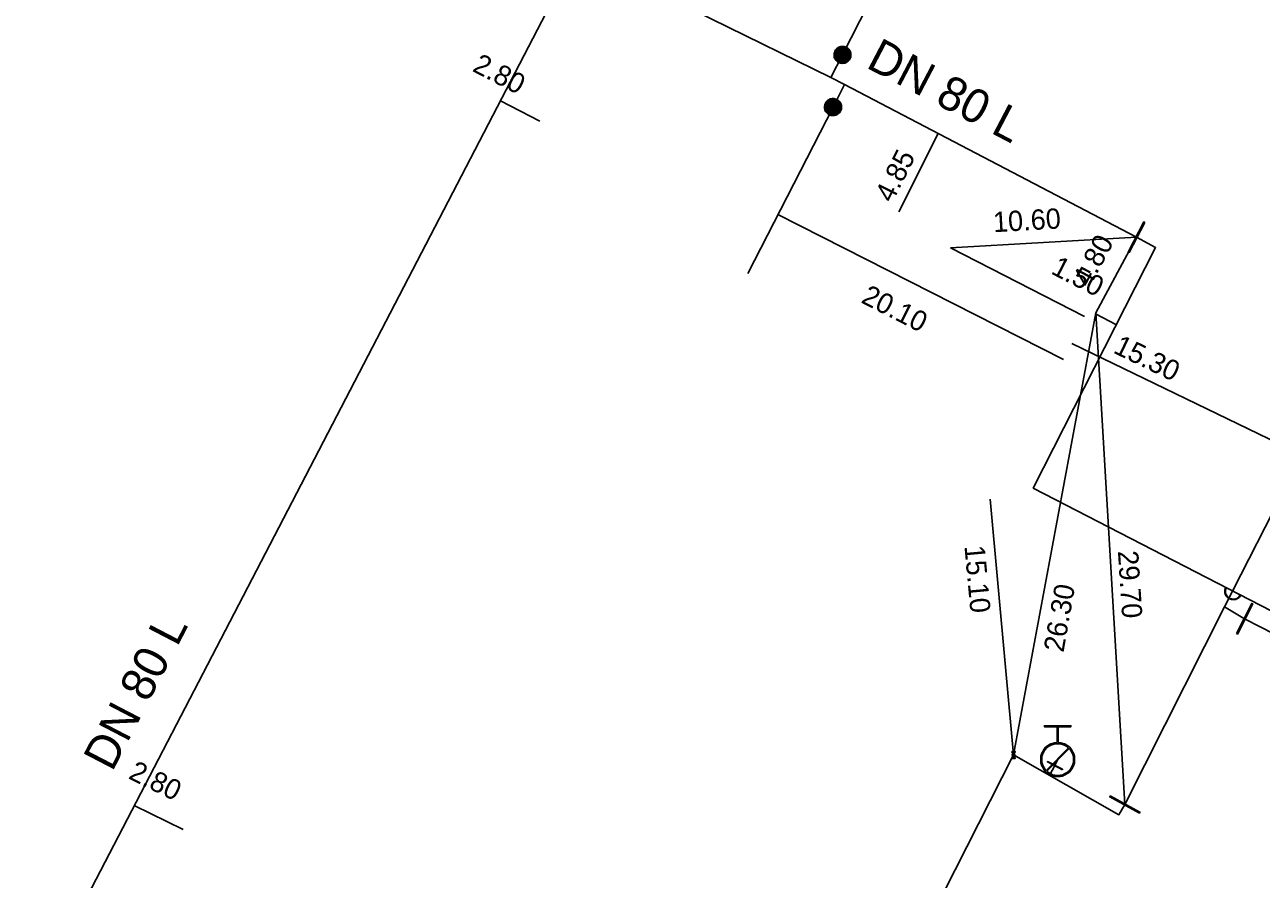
# Model space of a CAD drawing. Extents: x -820257 to -819974, y -1070894 to -1070484.
# Drawn here: x -820182.3 to -820109.2, y -1070567.6 to -1070517.1 of the extents above; entities that cross this region are included whole.
import ezdxf

# ---------------------------------------------------------------- set-up
doc = ezdxf.new("R2010")
doc.units = 0
for name, color, linetype in [('Hyd-odbočka', 7, 'Continuous'), ('Hyd-šoupě', 7, 'Continuous'), ('Hydrant', 7, 'Continuous'), ('Lomový bod vodovodu', 7, 'Continuous'), ('Nepropojené křížení vodovodu', 7, 'Continuous'), ('Oměrka vodovodu', 7, 'Continuous'), ('Oměrka-text', 7, 'Continuous'), ('Přípojka vodovodu', 7, 'Continuous'), ('Přípojkový uzávěr', 7, 'Continuous'), ('Roz-řad', 7, 'Continuous'), ('Roz-řad-popis základní', 7, 'Continuous'), ('Řad-šoupě', 7, 'Continuous')]:
    doc.layers.add(name, color=color, linetype=linetype)

msp = doc.modelspace()

# ---------------------------------------------------------------- linework, layer by layer
at = {"layer": 'Hyd-odbočka'}
for p, q in [((-820121.39, -1070560.91), (-820121.23, -1070560.55)), ((-820121.717, -1070561.486), (-820121.39, -1070560.91))]:
    msp.add_line(p, q, dxfattribs=at)
at = {"layer": 'Hyd-šoupě'}
msp.add_lwpolyline([(-820120.952, -1070561.152), (-820121.842, -1070560.696), (-820121.828, -1070560.668), (-820120.938, -1070561.124), (-820120.952, -1070561.152)], dxfattribs=at)
at = {"layer": 'Hydrant'}
for points in [[(-820121.261, -1070559.55), (-820121.261, -1070558.613), (-820122.011, -1070558.613), (-820122.011, -1070558.55), (-820120.449, -1070558.55), (-820120.449, -1070558.613), (-820121.199, -1070558.613), (-820121.199, -1070559.55)], [(-820121.916, -1070561.193), (-820120.587, -1070559.864)], [(-820120.544, -1070559.907), (-820121.873, -1070561.238)]]:
    msp.add_lwpolyline(points, dxfattribs=at)
for points in [[(-820121.199, -1070559.55), (-820120.962, -1070559.558), (-820120.738, -1070559.679), (-820120.5, -1070559.808), (-820120.365, -1070560.048), (-820120.23, -1070560.288), (-820120.23, -1070560.55), (-820120.23, -1070560.81), (-820120.362, -1070561.048), (-820120.494, -1070561.286), (-820120.732, -1070561.418), (-820120.97, -1070561.55), (-820121.23, -1070561.55), (-820121.49, -1070561.55), (-820121.728, -1070561.418), (-820121.966, -1070561.286), (-820122.098, -1070561.048), (-820122.23, -1070560.81), (-820122.23, -1070560.55), (-820122.23, -1070560.288), (-820122.095, -1070560.048), (-820121.96, -1070559.808), (-820121.722, -1070559.679), (-820121.5, -1070559.558), (-820121.261, -1070559.55)], [(-820120.587, -1070559.864), (-820120.669, -1070559.788), (-820120.769, -1070559.734), (-820120.994, -1070559.613), (-820121.23, -1070559.613), (-820121.466, -1070559.613), (-820121.691, -1070559.734), (-820121.916, -1070559.855), (-820122.042, -1070560.079), (-820122.168, -1070560.304), (-820122.168, -1070560.55), (-820122.168, -1070560.794), (-820122.043, -1070561.017), (-820121.99, -1070561.114), (-820121.916, -1070561.193)], [(-820121.873, -1070561.238), (-820121.794, -1070561.31), (-820121.697, -1070561.363), (-820121.474, -1070561.488), (-820121.23, -1070561.488), (-820120.986, -1070561.488), (-820120.762, -1070561.363), (-820120.539, -1070561.239), (-820120.416, -1070561.017), (-820120.293, -1070560.794), (-820120.293, -1070560.55), (-820120.293, -1070560.304), (-820120.419, -1070560.079), (-820120.474, -1070559.984), (-820120.544, -1070559.907)]]:
    msp.add_open_spline(points, degree=3, dxfattribs=at)
at = {"layer": 'Lomový bod vodovodu'}
for points in [[(-820123.878, -1070560.216), (-820123.94, -1070560.08), (-820123.74, -1070560.08), (-820123.803, -1070560.216)], [(-820123.818, -1070560.209), (-820123.764, -1070560.093), (-820123.918, -1070560.093), (-820123.863, -1070560.209)], [(-820123.803, -1070560.344), (-820123.74, -1070560.48), (-820123.94, -1070560.48), (-820123.878, -1070560.344)], [(-820123.863, -1070560.351), (-820123.918, -1070560.468), (-820123.764, -1070560.468), (-820123.818, -1070560.351)], [(-820123.872, -1070560.333), (-820123.848, -1070560.28), (-820123.872, -1070560.227)], [(-820123.858, -1070560.22), (-820123.84, -1070560.258), (-820123.823, -1070560.22)], [(-820123.823, -1070560.34), (-820123.84, -1070560.302), (-820123.858, -1070560.34)], [(-820123.808, -1070560.227), (-820123.832, -1070560.28), (-820123.808, -1070560.333)]]:
    msp.add_lwpolyline(points, dxfattribs=at)
for points in [[(-820123.878, -1070560.344), (-820123.895, -1070560.335), (-820123.905, -1070560.317), (-820123.915, -1070560.3), (-820123.915, -1070560.28), (-820123.915, -1070560.26), (-820123.905, -1070560.243), (-820123.895, -1070560.225), (-820123.878, -1070560.216)], [(-820123.872, -1070560.227), (-820123.886, -1070560.235), (-820123.894, -1070560.249), (-820123.902, -1070560.264), (-820123.902, -1070560.28), (-820123.902, -1070560.296), (-820123.894, -1070560.311), (-820123.886, -1070560.325), (-820123.872, -1070560.333)], [(-820123.863, -1070560.209), (-820123.852, -1070560.205), (-820123.84, -1070560.205), (-820123.829, -1070560.205), (-820123.818, -1070560.209)], [(-820123.818, -1070560.351), (-820123.828, -1070560.355), (-820123.84, -1070560.355), (-820123.852, -1070560.355), (-820123.863, -1070560.351)], [(-820123.823, -1070560.22), (-820123.831, -1070560.218), (-820123.84, -1070560.218), (-820123.849, -1070560.218), (-820123.858, -1070560.22)], [(-820123.858, -1070560.34), (-820123.849, -1070560.342), (-820123.84, -1070560.342), (-820123.831, -1070560.342), (-820123.823, -1070560.34)], [(-820123.808, -1070560.333), (-820123.794, -1070560.325), (-820123.786, -1070560.311), (-820123.778, -1070560.296), (-820123.778, -1070560.28), (-820123.778, -1070560.264), (-820123.786, -1070560.249), (-820123.794, -1070560.235), (-820123.808, -1070560.227)], [(-820123.803, -1070560.216), (-820123.785, -1070560.225), (-820123.775, -1070560.243), (-820123.765, -1070560.26), (-820123.765, -1070560.28), (-820123.765, -1070560.3), (-820123.775, -1070560.317), (-820123.785, -1070560.335), (-820123.803, -1070560.344)]]:
    msp.add_open_spline(points, degree=3, dxfattribs=at)
at = {"layer": 'Nepropojené křížení vodovodu'}
for points in [[(-820111.287, -1070550.366), (-820111.26, -1070550.38)], [(-820110.426, -1070550.81), (-820110.399, -1070550.824)]]:
    msp.add_lwpolyline(points, dxfattribs=at)
for points in [[(-820110.399, -1070550.824), (-820110.458, -1070550.94), (-820110.573, -1070551.016), (-820110.688, -1070551.092), (-820110.824, -1070551.095), (-820110.959, -1070551.097), (-820111.072, -1070551.039), (-820111.184, -1070550.982), (-820111.26, -1070550.87), (-820111.337, -1070550.758), (-820111.342, -1070550.62), (-820111.347, -1070550.482), (-820111.287, -1070550.366)], [(-820111.26, -1070550.38), (-820111.316, -1070550.489), (-820111.311, -1070550.619), (-820111.306, -1070550.747), (-820111.234, -1070550.852), (-820111.162, -1070550.958), (-820111.057, -1070551.012), (-820110.952, -1070551.066), (-820110.825, -1070551.063), (-820110.697, -1070551.061), (-820110.59, -1070550.99), (-820110.482, -1070550.918), (-820110.426, -1070550.81)]]:
    msp.add_open_spline(points, degree=3, dxfattribs=at)
at = {"layer": 'Oměrka vodovodu'}
for p, q in [((-820154.182, -1070521.591), (-820151.864, -1070522.792)), ((-820130.619, -1070528.169), (-820128.299, -1070523.527)), ((-820137.776, -1070528.315), (-820120.893, -1070536.892)), ((-820127.57, -1070530.3), (-820116.57, -1070529.663)), ((-820116.57, -1070529.663), (-820118.97, -1070534.14)), ((-820119.65, -1070534.36), (-820127.57, -1070530.3)), ((-820118.97, -1070534.14), (-820123.84, -1070560.28)), ((-820119.001, -1070534.2), (-820117.76, -1070534.842)), ((-820118.97, -1070534.14), (-820117.26, -1070563.21)), ((-820120.401, -1070535.954), (-820106.813, -1070542.526)), ((-820125.228, -1070545.148), (-820123.84, -1070560.28)), ((-820175.84, -1070563.271), (-820172.949, -1070564.686))]:
    msp.add_line(p, q, dxfattribs=at)
at = {"layer": 'Přípojka vodovodu'}
for points in [[(-820134.64, -1070520.216), (-820133.959, -1070518.88), (-820120.148, -1070491.785)], [(-820133.832, -1070520.633), (-820134.516, -1070521.968), (-820139.563, -1070531.808)]]:
    msp.add_lwpolyline(points, dxfattribs=at)
at = {"layer": 'Přípojkový uzávěr'}
for points in [[(-820134.405, -1070518.653), (-820134.347, -1070518.541), (-820134.235, -1070518.464), (-820134.124, -1070518.386), (-820133.986, -1070518.381), (-820133.848, -1070518.375), (-820133.731, -1070518.435), (-820133.616, -1070518.494), (-820133.54, -1070518.607), (-820133.464, -1070518.719), (-820133.459, -1070518.855), (-820133.454, -1070518.991), (-820133.514, -1070519.108), (-820133.573, -1070519.223), (-820133.685, -1070519.299), (-820133.798, -1070519.375), (-820133.934, -1070519.38), (-820134.07, -1070519.385), (-820134.186, -1070519.325), (-820134.302, -1070519.266), (-820134.379, -1070519.152), (-820134.456, -1070519.037), (-820134.459, -1070518.901), (-820134.462, -1070518.766), (-820134.405, -1070518.653)], [(-820134.363, -1070518.674), (-820134.415, -1070518.776), (-820134.412, -1070518.899), (-820134.409, -1070519.022), (-820134.34, -1070519.126), (-820134.27, -1070519.23), (-820134.164, -1070519.284), (-820134.06, -1070519.337), (-820133.937, -1070519.333), (-820133.814, -1070519.329), (-820133.711, -1070519.26), (-820133.609, -1070519.191), (-820133.555, -1070519.086), (-820133.502, -1070518.981), (-820133.506, -1070518.857), (-820133.51, -1070518.734), (-820133.579, -1070518.632), (-820133.648, -1070518.53), (-820133.753, -1070518.476), (-820133.858, -1070518.423), (-820133.983, -1070518.428), (-820134.109, -1070518.433), (-820134.21, -1070518.503), (-820134.311, -1070518.573), (-820134.363, -1070518.674)], [(-820134.332, -1070518.69), (-820134.284, -1070518.596), (-820134.191, -1070518.531), (-820134.097, -1070518.467), (-820133.982, -1070518.462), (-820133.866, -1070518.457), (-820133.768, -1070518.507), (-820133.671, -1070518.556), (-820133.607, -1070518.651), (-820133.544, -1070518.745), (-820133.54, -1070518.859), (-820133.536, -1070518.973), (-820133.586, -1070519.071), (-820133.635, -1070519.167), (-820133.73, -1070519.231), (-820133.824, -1070519.295), (-820133.938, -1070519.299), (-820134.052, -1070519.303), (-820134.149, -1070519.253), (-820134.247, -1070519.203), (-820134.311, -1070519.108), (-820134.375, -1070519.012), (-820134.378, -1070518.898), (-820134.38, -1070518.784), (-820134.332, -1070518.69)], [(-820134.293, -1070518.71), (-820134.364, -1070518.85), (-820134.316, -1070518.996), (-820134.268, -1070519.143), (-820134.129, -1070519.214), (-820133.991, -1070519.285), (-820133.843, -1070519.237), (-820133.695, -1070519.189), (-820133.625, -1070519.051), (-820133.554, -1070518.912), (-820133.602, -1070518.764), (-820133.65, -1070518.617), (-820133.788, -1070518.546), (-820133.927, -1070518.475), (-820134.074, -1070518.523), (-820134.222, -1070518.57), (-820134.293, -1070518.71)], [(-820134.252, -1070518.731), (-820134.19, -1070518.609), (-820134.061, -1070518.568), (-820133.932, -1070518.526), (-820133.811, -1070518.588), (-820133.69, -1070518.65), (-820133.648, -1070518.779), (-820133.606, -1070518.908), (-820133.668, -1070519.029), (-820133.73, -1070519.151), (-820133.859, -1070519.193), (-820133.988, -1070519.235), (-820134.109, -1070519.173), (-820134.231, -1070519.111), (-820134.273, -1070518.982), (-820134.315, -1070518.853), (-820134.252, -1070518.731)], [(-820134.217, -1070518.749), (-820134.272, -1070518.856), (-820134.235, -1070518.97), (-820134.198, -1070519.083), (-820134.091, -1070519.137), (-820133.985, -1070519.192), (-820133.871, -1070519.155), (-820133.758, -1070519.118), (-820133.703, -1070519.011), (-820133.649, -1070518.905), (-820133.686, -1070518.791), (-820133.723, -1070518.678), (-820133.829, -1070518.623), (-820133.936, -1070518.569), (-820134.049, -1070518.605), (-820134.162, -1070518.642), (-820134.217, -1070518.749)], [(-820134.182, -1070518.767), (-820134.134, -1070518.673), (-820134.036, -1070518.642), (-820133.937, -1070518.61), (-820133.845, -1070518.657), (-820133.753, -1070518.704), (-820133.721, -1070518.803), (-820133.689, -1070518.901), (-820133.736, -1070518.994), (-820133.783, -1070519.086), (-820133.882, -1070519.118), (-820133.98, -1070519.15), (-820134.072, -1070519.103), (-820134.165, -1070519.056), (-820134.197, -1070518.958), (-820134.229, -1070518.86), (-820134.182, -1070518.767)], [(-820134.14, -1070518.788), (-820134.179, -1070518.863), (-820134.153, -1070518.943), (-820134.127, -1070519.023), (-820134.052, -1070519.061), (-820133.977, -1070519.099), (-820133.897, -1070519.074), (-820133.817, -1070519.048), (-820133.779, -1070518.972), (-820133.74, -1070518.898), (-820133.766, -1070518.818), (-820133.792, -1070518.738), (-820133.867, -1070518.699), (-820133.942, -1070518.661), (-820134.022, -1070518.687), (-820134.102, -1070518.713), (-820134.14, -1070518.788)], [(-820134.11, -1070518.804), (-820134.078, -1070518.741), (-820134.012, -1070518.719), (-820133.946, -1070518.698), (-820133.883, -1070518.73), (-820133.82, -1070518.762), (-820133.799, -1070518.828), (-820133.778, -1070518.894), (-820133.81, -1070518.957), (-820133.841, -1070519.019), (-820133.907, -1070519.041), (-820133.973, -1070519.062), (-820134.036, -1070519.03), (-820134.099, -1070518.998), (-820134.12, -1070518.932), (-820134.142, -1070518.866), (-820134.11, -1070518.804)], [(-820134.07, -1070518.824), (-820134.094, -1070518.87), (-820134.078, -1070518.919), (-820134.062, -1070518.968), (-820134.016, -1070518.991), (-820133.97, -1070519.015), (-820133.92, -1070518.999), (-820133.871, -1070518.983), (-820133.848, -1070518.937), (-820133.824, -1070518.891), (-820133.84, -1070518.841), (-820133.856, -1070518.792), (-820133.902, -1070518.769), (-820133.948, -1070518.745), (-820133.997, -1070518.761), (-820134.047, -1070518.777), (-820134.07, -1070518.824)], [(-820134.029, -1070518.845), (-820134.014, -1070518.815), (-820133.983, -1070518.805), (-820133.953, -1070518.796), (-820133.924, -1070518.811), (-820133.895, -1070518.825), (-820133.885, -1070518.856), (-820133.874, -1070518.886), (-820133.89, -1070518.916), (-820133.904, -1070518.945), (-820133.935, -1070518.955), (-820133.966, -1070518.965), (-820133.995, -1070518.95), (-820134.024, -1070518.935), (-820134.034, -1070518.904), (-820134.043, -1070518.874), (-820134.029, -1070518.845)], [(-820134.001, -1070518.859), (-820134.01, -1070518.876), (-820134.004, -1070518.895), (-820133.998, -1070518.913), (-820133.98, -1070518.922), (-820133.963, -1070518.931), (-820133.945, -1070518.925), (-820133.926, -1070518.919), (-820133.917, -1070518.902), (-820133.908, -1070518.884), (-820133.914, -1070518.866), (-820133.92, -1070518.847), (-820133.938, -1070518.839), (-820133.956, -1070518.829), (-820133.974, -1070518.835), (-820133.992, -1070518.841), (-820134.001, -1070518.859)], [(-820134.962, -1070521.74), (-820134.904, -1070521.628), (-820134.792, -1070521.551), (-820134.681, -1070521.474), (-820134.543, -1070521.468), (-820134.405, -1070521.463), (-820134.288, -1070521.523), (-820134.173, -1070521.582), (-820134.097, -1070521.695), (-820134.021, -1070521.807), (-820134.016, -1070521.944), (-820134.012, -1070522.08), (-820134.071, -1070522.196), (-820134.13, -1070522.311), (-820134.243, -1070522.387), (-820134.356, -1070522.463), (-820134.492, -1070522.468), (-820134.628, -1070522.472), (-820134.744, -1070522.413), (-820134.86, -1070522.353), (-820134.937, -1070522.239), (-820135.013, -1070522.124), (-820135.016, -1070521.989), (-820135.019, -1070521.853), (-820134.962, -1070521.74)], [(-820134.92, -1070521.762), (-820134.972, -1070521.863), (-820134.969, -1070521.986), (-820134.967, -1070522.11), (-820134.897, -1070522.213), (-820134.828, -1070522.317), (-820134.722, -1070522.371), (-820134.617, -1070522.425), (-820134.495, -1070522.421), (-820134.372, -1070522.417), (-820134.269, -1070522.348), (-820134.167, -1070522.279), (-820134.113, -1070522.174), (-820134.059, -1070522.069), (-820134.063, -1070521.946), (-820134.067, -1070521.822), (-820134.136, -1070521.72), (-820134.205, -1070521.618), (-820134.31, -1070521.564), (-820134.415, -1070521.51), (-820134.54, -1070521.515), (-820134.666, -1070521.52), (-820134.767, -1070521.59), (-820134.868, -1070521.66), (-820134.92, -1070521.762)], [(-820134.89, -1070521.777), (-820134.841, -1070521.683), (-820134.748, -1070521.619), (-820134.654, -1070521.554), (-820134.539, -1070521.549), (-820134.423, -1070521.545), (-820134.325, -1070521.595), (-820134.228, -1070521.644), (-820134.165, -1070521.739), (-820134.101, -1070521.833), (-820134.097, -1070521.947), (-820134.094, -1070522.061), (-820134.144, -1070522.159), (-820134.193, -1070522.255), (-820134.288, -1070522.319), (-820134.382, -1070522.383), (-820134.496, -1070522.387), (-820134.61, -1070522.39), (-820134.707, -1070522.341), (-820134.805, -1070522.291), (-820134.869, -1070522.195), (-820134.933, -1070522.099), (-820134.935, -1070521.985), (-820134.938, -1070521.871), (-820134.89, -1070521.777)], [(-820134.851, -1070521.798), (-820134.922, -1070521.937), (-820134.874, -1070522.084), (-820134.825, -1070522.231), (-820134.687, -1070522.302), (-820134.548, -1070522.372), (-820134.401, -1070522.324), (-820134.253, -1070522.277), (-820134.183, -1070522.139), (-820134.112, -1070522), (-820134.159, -1070521.852), (-820134.207, -1070521.705), (-820134.345, -1070521.634), (-820134.484, -1070521.563), (-820134.631, -1070521.61), (-820134.779, -1070521.657), (-820134.851, -1070521.798)], [(-820134.81, -1070521.819), (-820134.747, -1070521.696), (-820134.618, -1070521.655), (-820134.49, -1070521.614), (-820134.368, -1070521.676), (-820134.247, -1070521.738), (-820134.205, -1070521.867), (-820134.164, -1070521.996), (-820134.226, -1070522.117), (-820134.288, -1070522.239), (-820134.417, -1070522.281), (-820134.546, -1070522.322), (-820134.667, -1070522.26), (-820134.788, -1070522.198), (-820134.83, -1070522.069), (-820134.872, -1070521.94), (-820134.81, -1070521.819)], [(-820134.775, -1070521.837), (-820134.829, -1070521.944), (-820134.792, -1070522.057), (-820134.756, -1070522.17), (-820134.649, -1070522.225), (-820134.543, -1070522.279), (-820134.429, -1070522.243), (-820134.315, -1070522.206), (-820134.261, -1070522.099), (-820134.206, -1070521.993), (-820134.243, -1070521.879), (-820134.28, -1070521.766), (-820134.386, -1070521.711), (-820134.493, -1070521.657), (-820134.606, -1070521.693), (-820134.72, -1070521.729), (-820134.775, -1070521.837)], [(-820134.739, -1070521.854), (-820134.691, -1070521.761), (-820134.593, -1070521.729), (-820134.495, -1070521.698), (-820134.402, -1070521.745), (-820134.31, -1070521.792), (-820134.278, -1070521.891), (-820134.247, -1070521.989), (-820134.294, -1070522.082), (-820134.341, -1070522.174), (-820134.439, -1070522.206), (-820134.538, -1070522.237), (-820134.63, -1070522.19), (-820134.722, -1070522.143), (-820134.755, -1070522.045), (-820134.787, -1070521.947), (-820134.739, -1070521.854)], [(-820134.698, -1070521.875), (-820134.736, -1070521.95), (-820134.711, -1070522.03), (-820134.685, -1070522.11), (-820134.61, -1070522.149), (-820134.534, -1070522.187), (-820134.454, -1070522.161), (-820134.375, -1070522.135), (-820134.336, -1070522.06), (-820134.298, -1070521.985), (-820134.324, -1070521.905), (-820134.349, -1070521.825), (-820134.425, -1070521.787), (-820134.5, -1070521.748), (-820134.58, -1070521.774), (-820134.659, -1070521.8), (-820134.698, -1070521.875)], [(-820134.667, -1070521.891), (-820134.635, -1070521.828), (-820134.569, -1070521.807), (-820134.503, -1070521.786), (-820134.44, -1070521.818), (-820134.378, -1070521.85), (-820134.356, -1070521.916), (-820134.335, -1070521.982), (-820134.367, -1070522.044), (-820134.399, -1070522.107), (-820134.465, -1070522.128), (-820134.531, -1070522.15), (-820134.594, -1070522.118), (-820134.656, -1070522.086), (-820134.678, -1070522.02), (-820134.699, -1070521.954), (-820134.667, -1070521.891)], [(-820134.628, -1070521.911), (-820134.651, -1070521.957), (-820134.635, -1070522.006), (-820134.619, -1070522.055), (-820134.573, -1070522.079), (-820134.527, -1070522.102), (-820134.478, -1070522.086), (-820134.429, -1070522.071), (-820134.405, -1070522.025), (-820134.381, -1070521.978), (-820134.397, -1070521.929), (-820134.413, -1070521.88), (-820134.459, -1070521.856), (-820134.506, -1070521.833), (-820134.555, -1070521.848), (-820134.604, -1070521.864), (-820134.628, -1070521.911)], [(-820134.586, -1070521.932), (-820134.571, -1070521.903), (-820134.541, -1070521.893), (-820134.511, -1070521.883), (-820134.481, -1070521.898), (-820134.452, -1070521.913), (-820134.442, -1070521.944), (-820134.432, -1070521.974), (-820134.447, -1070522.004), (-820134.462, -1070522.032), (-820134.493, -1070522.042), (-820134.523, -1070522.052), (-820134.552, -1070522.038), (-820134.582, -1070522.022), (-820134.591, -1070521.992), (-820134.601, -1070521.961), (-820134.586, -1070521.932)], [(-820134.558, -1070521.947), (-820134.567, -1070521.964), (-820134.561, -1070521.982), (-820134.556, -1070522.001), (-820134.538, -1070522.01), (-820134.521, -1070522.019), (-820134.502, -1070522.013), (-820134.484, -1070522.007), (-820134.475, -1070521.989), (-820134.466, -1070521.972), (-820134.472, -1070521.953), (-820134.478, -1070521.935), (-820134.495, -1070521.926), (-820134.513, -1070521.917), (-820134.531, -1070521.923), (-820134.549, -1070521.929), (-820134.558, -1070521.947)]]:
    msp.add_open_spline(points, degree=3, dxfattribs=at)
at = {"layer": 'Roz-řad'}
for p, q in [((-820111.356, -1070551.519), (-820090.584, -1070510.68)), ((-820117.26, -1070563.21), (-820111.356, -1070551.519)), ((-820111.356, -1070551.519), (-820110.178, -1070552.224)), ((-820110.178, -1070552.224), (-820031.976, -1070592.492))]:
    msp.add_line(p, q, dxfattribs=at)
for points in [[(-820149.629, -1070512.816), (-820182.322, -1070575.745), (-820181.435, -1070576.285)], [(-820148.797, -1070513.257), (-820134.64, -1070520.216), (-820133.832, -1070520.633), (-820116.57, -1070529.663)], [(-820116.57, -1070529.663), (-820115.438, -1070530.28), (-820122.673, -1070544.495), (-820079.076, -1070566.966)], [(-820173.82, -1070657.97), (-820165.56, -1070640.89), (-820158.15, -1070622.33), (-820156.54, -1070616.06), (-820145.77, -1070596.81), (-820140.37, -1070592.75), (-820129.37, -1070571.15), (-820123.84, -1070560.28), (-820117.608, -1070563.82), (-820117.26, -1070563.21)]]:
    msp.add_lwpolyline(points, dxfattribs=at)
at = {"layer": 'Řad-šoupě'}
for points in [[(-820116.084, -1070528.788), (-820117, -1070530.566), (-820117.056, -1070530.537), (-820116.14, -1070528.759), (-820116.084, -1070528.788)], [(-820110.657, -1070553.101), (-820109.753, -1070551.317), (-820109.697, -1070551.345), (-820110.602, -1070553.129), (-820110.657, -1070553.101)], [(-820118.124, -1070562.705), (-820116.366, -1070563.66), (-820116.396, -1070563.715), (-820118.154, -1070562.76), (-820118.124, -1070562.705)]]:
    msp.add_lwpolyline(points, dxfattribs=at)

# ---------------------------------------------------------------- texts
at = {"layer": 'Oměrka-text'}
for s, rotation, p in [(' 2.80', 332.61048, (-820156.302, -1070519.61)), (' 4.85', 63.4431, (-820131.214, -1070528.077)), ('10.60', 3.31713, (-820125.024, -1070529.371)), (' 4.80', 61.80884, (-820119.567, -1070533.087)), (' 1.50', 332.6811, (-820122.083, -1070531.582)), ('20.10', 333.06825, (-820132.917, -1070533.5)), ('15.30', 334.18869, (-820118.002, -1070536.472)), ('15.10', 275.24085, (-820126.748, -1070547.932)), ('29.70', 273.69432, (-820117.671, -1070548.226)), ('26.30', 80.06936, (-820120.889, -1070554.251)), (' 2.80', 333.92055, (-820176.648, -1070561.454))]:
    msp.add_text(s, height=1.2, rotation=rotation, dxfattribs=at).set_placement(p)
at = {"layer": 'Roz-řad-popis základní'}
for rotation, p in [(332.38551, (-820132.63, -1070519.6)), (62.54734, (-820177.151, -1070561.319))]:
    msp.add_text('DN 80 L', height=2, rotation=rotation, dxfattribs=at).set_placement(p)

doc.saveas('drawing.dxf')
